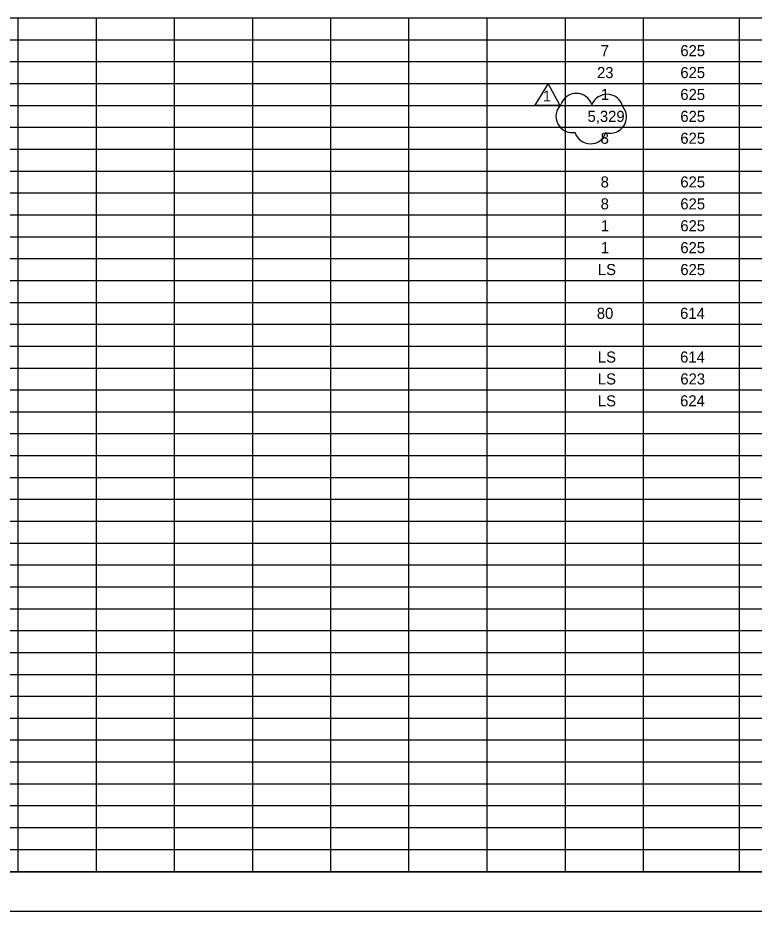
# Model space of a CAD drawing. Extents: x 0 to 34, y 0 to 22.
# Drawn here: x 7.49 to 16.91, y 0 to 11.42 of the extents above; entities that cross this region are included whole.
import ezdxf

# ---------------------------------------------------------------- set-up
doc = ezdxf.new("R2010")
doc.units = 0
for name, color, linetype in [('Default', 7, 'Continuous'), ('SH_Border', 7, 'Continuous'), ('SH_Cut_Line', 7, 'Continuous'), ('SH_Text', 7, 'Continuous')]:
    doc.layers.add(name, color=color, linetype=linetype)

msp = doc.modelspace()

# ---------------------------------------------------------------- linework, layer by layer
at = {"layer": 'Default'}
msp.add_lwpolyline([(14.273, 10.587), (14.102, 10.308), (14.422, 10.307)], close=True, dxfattribs=at)
for centre, start, end in [((14.633, 10.251), 17.5, 162.5), ((15.026, 10.239), 14.1039, 159.1039), ((14.581, 10.165), 134.5743, 279.5743), ((15.067, 10.158), 254.4905, 39.4905), ((14.814, 10.022), 197.0681, 342.0681)]:
    msp.add_arc(centre, 0.208, start, end, dxfattribs=at)
at = {"layer": 'SH_Border'}
msp.add_lwpolyline([(1.5, 21.5), (33.5, 21.5), (33.5, 0.5), (1.5, 0.5)], close=True, dxfattribs=at)
at = {"layer": 'SH_Cut_Line'}
msp.add_lwpolyline([(0, 0), (34, 0), (34, 22), (0, 22)], close=True, dxfattribs=at)
at = {"layer": 'SH_Text'}
for p, q in [((6.496, 11.424), (7.495, 11.424)), ((7.495, 11.424), (8.494, 11.424)), ((7.495, 11.424), (7.495, 10.305)), ((8.494, 11.424), (13.49, 11.424)), ((8.494, 11.424), (8.494, 10.305)), ((9.493, 11.424), (9.493, 10.305)), ((10.492, 11.424), (10.492, 10.305)), ((11.491, 11.424), (11.491, 10.305)), ((12.49, 11.424), (12.49, 10.305)), ((13.49, 11.424), (31.057, 11.424)), ((13.49, 11.424), (13.49, 10.305)), ((14.489, 11.424), (14.489, 10.305)), ((15.488, 11.424), (15.488, 10.305)), ((16.715, 11.424), (16.715, 10.305)), ((6.496, 11.145), (7.495, 11.145)), ((7.495, 11.145), (8.494, 11.145)), ((8.494, 11.145), (13.49, 11.145)), ((13.49, 11.145), (31.057, 11.145)), ((6.496, 10.865), (7.495, 10.865)), ((7.495, 10.865), (8.494, 10.865)), ((8.494, 10.865), (13.49, 10.865)), ((13.49, 10.865), (31.057, 10.865)), ((6.496, 10.585), (7.495, 10.585)), ((7.495, 10.585), (8.494, 10.585)), ((8.494, 10.585), (13.49, 10.585)), ((13.49, 10.585), (31.057, 10.585)), ((6.496, 10.305), (7.495, 10.305)), ((7.495, 10.305), (8.494, 10.305)), ((7.495, 10.305), (7.495, 10.025)), ((8.494, 10.305), (13.49, 10.305)), ((8.494, 10.305), (8.494, 10.025)), ((9.493, 10.305), (9.493, 10.025)), ((10.492, 10.305), (10.492, 10.025)), ((11.491, 10.305), (11.491, 10.025)), ((12.49, 10.305), (12.49, 10.025)), ((13.49, 10.305), (31.057, 10.305)), ((13.49, 10.305), (13.49, 10.025)), ((14.489, 10.305), (14.489, 10.025)), ((15.488, 10.305), (15.488, 10.025)), ((16.715, 10.305), (16.715, 10.025)), ((6.496, 10.025), (7.495, 10.025)), ((7.495, 10.025), (8.494, 10.025)), ((7.495, 10.025), (7.495, 9.745)), ((8.494, 10.025), (13.49, 10.025)), ((8.494, 10.025), (8.494, 9.745)), ((9.493, 10.025), (9.493, 9.745)), ((10.492, 10.025), (10.492, 9.745)), ((11.491, 10.025), (11.491, 9.745)), ((12.49, 10.025), (12.49, 9.745)), ((13.49, 10.025), (31.057, 10.025)), ((13.49, 10.025), (13.49, 9.745)), ((14.489, 10.025), (14.489, 9.745)), ((15.488, 10.025), (15.488, 9.745)), ((16.715, 10.025), (16.715, 9.745)), ((6.496, 9.745), (7.495, 9.745)), ((7.495, 9.745), (8.494, 9.745)), ((7.495, 9.745), (7.495, 8.906)), ((8.494, 9.745), (13.49, 9.745)), ((8.494, 9.745), (8.494, 8.906)), ((9.493, 9.745), (9.493, 8.906)), ((10.492, 9.745), (10.492, 8.906)), ((11.491, 9.745), (11.491, 8.906)), ((12.49, 9.745), (12.49, 8.906)), ((13.49, 9.745), (31.057, 9.745)), ((13.49, 9.745), (13.49, 8.906)), ((14.489, 9.745), (14.489, 8.906)), ((15.488, 9.745), (15.488, 8.906)), ((16.715, 9.745), (16.715, 8.906)), ((6.496, 9.465), (7.495, 9.465)), ((7.495, 9.465), (8.494, 9.465)), ((8.494, 9.465), (13.49, 9.465)), ((13.49, 9.465), (31.057, 9.465)), ((6.496, 9.185), (7.495, 9.185)), ((7.495, 9.185), (8.494, 9.185)), ((8.494, 9.185), (13.49, 9.185)), ((13.49, 9.185), (31.057, 9.185)), ((6.496, 8.906), (7.495, 8.906)), ((7.495, 8.906), (8.494, 8.906)), ((7.495, 8.906), (7.495, 8.346)), ((8.494, 8.906), (13.49, 8.906)), ((8.494, 8.906), (8.494, 8.346)), ((9.493, 8.906), (9.493, 8.346)), ((10.492, 8.906), (10.492, 8.346)), ((11.491, 8.906), (11.491, 8.346)), ((12.49, 8.906), (12.49, 8.346)), ((13.49, 8.906), (31.057, 8.906)), ((13.49, 8.906), (13.49, 8.346)), ((14.489, 8.906), (14.489, 8.346)), ((15.488, 8.906), (15.488, 8.346)), ((16.715, 8.906), (16.715, 8.346)), ((6.496, 8.626), (7.495, 8.626)), ((7.495, 8.626), (8.494, 8.626)), ((8.494, 8.626), (13.49, 8.626)), ((13.49, 8.626), (31.057, 8.626)), ((6.496, 8.346), (7.495, 8.346)), ((7.495, 8.346), (8.494, 8.346)), ((7.495, 8.346), (7.495, 7.506)), ((8.494, 8.346), (13.49, 8.346)), ((8.494, 8.346), (8.494, 7.506)), ((9.493, 8.346), (9.493, 7.506)), ((10.492, 8.346), (10.492, 7.506)), ((11.491, 8.346), (11.491, 7.506)), ((12.49, 8.346), (12.49, 7.506)), ((13.49, 8.346), (31.057, 8.346)), ((13.49, 8.346), (13.49, 7.506)), ((14.489, 8.346), (14.489, 7.506)), ((15.488, 8.346), (15.488, 7.506)), ((16.715, 8.346), (16.715, 7.506)), ((6.496, 8.066), (7.495, 8.066)), ((7.495, 8.066), (8.494, 8.066)), ((8.494, 8.066), (13.49, 8.066)), ((13.49, 8.066), (31.057, 8.066)), ((6.496, 7.786), (7.495, 7.786)), ((7.495, 7.786), (8.494, 7.786)), ((8.494, 7.786), (13.49, 7.786)), ((13.49, 7.786), (31.057, 7.786)), ((6.496, 7.506), (7.495, 7.506)), ((7.495, 7.506), (8.494, 7.506)), ((7.495, 7.506), (7.495, 6.946)), ((8.494, 7.506), (13.49, 7.506)), ((8.494, 7.506), (8.494, 6.946)), ((9.493, 7.506), (9.493, 6.946)), ((10.492, 7.506), (10.492, 6.946)), ((11.491, 7.506), (11.491, 6.946)), ((12.49, 7.506), (12.49, 6.946)), ((13.49, 7.506), (31.057, 7.506)), ((13.49, 7.506), (13.49, 6.946)), ((14.489, 7.506), (14.489, 6.946)), ((15.488, 7.506), (15.488, 6.946)), ((16.715, 7.506), (16.715, 6.946)), ((6.496, 7.226), (7.495, 7.226)), ((7.495, 7.226), (8.494, 7.226)), ((8.494, 7.226), (13.49, 7.226)), ((13.49, 7.226), (31.057, 7.226)), ((6.496, 6.946), (7.495, 6.946)), ((7.495, 6.946), (8.494, 6.946)), ((7.495, 6.946), (7.495, 6.107)), ((8.494, 6.946), (13.49, 6.946)), ((8.494, 6.946), (8.494, 6.107)), ((9.493, 6.946), (9.493, 6.107)), ((10.492, 6.946), (10.492, 6.107)), ((11.491, 6.946), (11.491, 6.107)), ((12.49, 6.946), (12.49, 6.107)), ((13.49, 6.946), (31.057, 6.946)), ((13.49, 6.946), (13.49, 6.107)), ((14.489, 6.946), (14.489, 6.107)), ((15.488, 6.946), (15.488, 6.107)), ((16.715, 6.946), (16.715, 6.107)), ((6.496, 6.667), (7.495, 6.667)), ((7.495, 6.667), (8.494, 6.667)), ((8.494, 6.667), (13.49, 6.667)), ((13.49, 6.667), (31.057, 6.667)), ((6.496, 6.387), (7.495, 6.387)), ((7.495, 6.387), (8.494, 6.387)), ((8.494, 6.387), (13.49, 6.387)), ((13.49, 6.387), (31.057, 6.387)), ((6.496, 6.107), (7.495, 6.107)), ((7.495, 6.107), (8.494, 6.107)), ((7.495, 6.107), (7.495, 4.987)), ((8.494, 6.107), (13.49, 6.107)), ((8.494, 6.107), (8.494, 4.987)), ((9.493, 6.107), (9.493, 4.987)), ((10.492, 6.107), (10.492, 4.987)), ((11.491, 6.107), (11.491, 4.987)), ((12.49, 6.107), (12.49, 4.987)), ((13.49, 6.107), (31.057, 6.107)), ((13.49, 6.107), (13.49, 4.987)), ((14.489, 6.107), (14.489, 4.987)), ((15.488, 6.107), (15.488, 4.987)), ((16.715, 6.107), (16.715, 4.987)), ((6.496, 5.827), (7.495, 5.827)), ((7.495, 5.827), (8.494, 5.827)), ((8.494, 5.827), (13.49, 5.827)), ((13.49, 5.827), (31.057, 5.827)), ((6.496, 5.547), (7.495, 5.547)), ((7.495, 5.547), (8.494, 5.547)), ((8.494, 5.547), (13.49, 5.547)), ((13.49, 5.547), (31.057, 5.547)), ((6.496, 5.267), (7.495, 5.267)), ((7.495, 5.267), (8.494, 5.267)), ((8.494, 5.267), (13.49, 5.267)), ((13.49, 5.267), (31.057, 5.267)), ((6.496, 4.987), (7.495, 4.987)), ((7.495, 4.987), (8.494, 4.987)), ((7.495, 4.987), (7.495, 4.707)), ((8.494, 4.987), (13.49, 4.987)), ((8.494, 4.987), (8.494, 4.707)), ((9.493, 4.987), (9.493, 4.707)), ((10.492, 4.987), (10.492, 4.707)), ((11.491, 4.987), (11.491, 4.707)), ((12.49, 4.987), (12.49, 4.707)), ((13.49, 4.987), (31.057, 4.987)), ((13.49, 4.987), (13.49, 4.707)), ((14.489, 4.987), (14.489, 4.707)), ((15.488, 4.987), (15.488, 4.707)), ((16.715, 4.987), (16.715, 4.707)), ((6.496, 4.707), (7.495, 4.707)), ((7.495, 4.707), (8.494, 4.707)), ((7.495, 4.707), (7.495, 3.588)), ((8.494, 4.707), (13.49, 4.707)), ((8.494, 4.707), (8.494, 3.588)), ((9.493, 4.707), (9.493, 3.588)), ((10.492, 4.707), (10.492, 3.588)), ((11.491, 4.707), (11.491, 3.588)), ((12.49, 4.707), (12.49, 3.588)), ((13.49, 4.707), (31.057, 4.707)), ((13.49, 4.707), (13.49, 3.588)), ((14.489, 4.707), (14.489, 3.588)), ((15.488, 4.707), (15.488, 3.588)), ((16.715, 4.707), (16.715, 3.588)), ((6.496, 4.428), (7.495, 4.428)), ((7.495, 4.428), (8.494, 4.428)), ((8.494, 4.428), (13.49, 4.428)), ((13.49, 4.428), (31.057, 4.428)), ((6.496, 4.148), (7.495, 4.148)), ((7.495, 4.148), (8.494, 4.148)), ((8.494, 4.148), (13.49, 4.148)), ((13.49, 4.148), (31.057, 4.148)), ((6.496, 3.868), (7.495, 3.868)), ((7.495, 3.868), (8.494, 3.868)), ((8.494, 3.868), (13.49, 3.868)), ((13.49, 3.868), (31.057, 3.868)), ((6.496, 3.588), (7.495, 3.588)), ((7.495, 3.588), (8.494, 3.588)), ((7.495, 3.588), (7.495, 3.308)), ((8.494, 3.588), (13.49, 3.588)), ((8.494, 3.588), (8.494, 3.308)), ((9.493, 3.588), (9.493, 3.308)), ((10.492, 3.588), (10.492, 3.308)), ((11.491, 3.588), (11.491, 3.308)), ((12.49, 3.588), (12.49, 3.308)), ((13.49, 3.588), (31.057, 3.588)), ((13.49, 3.588), (13.49, 3.308)), ((14.489, 3.588), (14.489, 3.308)), ((15.488, 3.588), (15.488, 3.308)), ((16.715, 3.588), (16.715, 3.308)), ((6.496, 3.308), (7.495, 3.308)), ((7.495, 3.308), (8.494, 3.308)), ((7.495, 3.308), (7.495, 2.189)), ((8.494, 3.308), (13.49, 3.308)), ((8.494, 3.308), (8.494, 2.189)), ((9.493, 3.308), (9.493, 2.189)), ((10.492, 3.308), (10.492, 2.189)), ((11.491, 3.308), (11.491, 2.189)), ((12.49, 3.308), (12.49, 2.189)), ((13.49, 3.308), (31.057, 3.308)), ((13.49, 3.308), (13.49, 2.189)), ((14.489, 3.308), (14.489, 2.189)), ((15.488, 3.308), (15.488, 2.189)), ((16.715, 3.308), (16.715, 2.189)), ((6.496, 3.028), (7.495, 3.028)), ((7.495, 3.028), (8.494, 3.028)), ((8.494, 3.028), (13.49, 3.028)), ((13.49, 3.028), (31.057, 3.028)), ((6.496, 2.748), (7.495, 2.748)), ((7.495, 2.748), (8.494, 2.748)), ((8.494, 2.748), (13.49, 2.748)), ((13.49, 2.748), (31.057, 2.748)), ((6.496, 2.468), (7.495, 2.468)), ((7.495, 2.468), (8.494, 2.468)), ((8.494, 2.468), (13.49, 2.468)), ((13.49, 2.468), (31.057, 2.468)), ((6.496, 2.189), (7.495, 2.189)), ((7.495, 2.189), (8.494, 2.189)), ((7.495, 2.189), (7.495, 1.909)), ((8.494, 2.189), (13.49, 2.189)), ((8.494, 2.189), (8.494, 1.909)), ((9.493, 2.189), (9.493, 1.909)), ((10.492, 2.189), (10.492, 1.909)), ((11.491, 2.189), (11.491, 1.909)), ((12.49, 2.189), (12.49, 1.909)), ((13.49, 2.189), (31.057, 2.189)), ((13.49, 2.189), (13.49, 1.909)), ((14.489, 2.189), (14.489, 1.909)), ((15.488, 2.189), (15.488, 1.909)), ((16.715, 2.189), (16.715, 1.909)), ((6.496, 1.909), (7.495, 1.909)), ((7.495, 1.909), (8.494, 1.909)), ((7.495, 1.909), (7.495, 0.789)), ((8.494, 1.909), (13.49, 1.909)), ((8.494, 1.909), (8.494, 0.789)), ((9.493, 1.909), (9.493, 0.789)), ((10.492, 1.909), (10.492, 0.789)), ((11.491, 1.909), (11.491, 0.789)), ((12.49, 1.909), (12.49, 0.789)), ((13.49, 1.909), (31.057, 1.909)), ((13.49, 1.909), (13.49, 0.789)), ((14.489, 1.909), (14.489, 0.789)), ((15.488, 1.909), (15.488, 0.789)), ((16.715, 1.909), (16.715, 0.789)), ((6.496, 1.629), (7.495, 1.629)), ((7.495, 1.629), (8.494, 1.629)), ((8.494, 1.629), (13.49, 1.629)), ((13.49, 1.629), (31.057, 1.629)), ((6.496, 1.349), (7.495, 1.349)), ((7.495, 1.349), (8.494, 1.349)), ((8.494, 1.349), (13.49, 1.349)), ((13.49, 1.349), (31.057, 1.349)), ((6.496, 1.069), (7.495, 1.069)), ((7.495, 1.069), (8.494, 1.069)), ((8.494, 1.069), (13.49, 1.069)), ((13.49, 1.069), (31.057, 1.069)), ((6.496, 0.789), (7.495, 0.789)), ((7.495, 0.789), (8.494, 0.789)), ((7.495, 0.789), (7.495, 0.509)), ((8.494, 0.789), (13.49, 0.789)), ((8.494, 0.789), (8.494, 0.509)), ((9.493, 0.789), (9.493, 0.509)), ((10.492, 0.789), (10.492, 0.509)), ((11.491, 0.789), (11.491, 0.509)), ((12.49, 0.789), (12.49, 0.509)), ((13.49, 0.789), (31.057, 0.789)), ((13.49, 0.789), (13.49, 0.509)), ((14.489, 0.789), (14.489, 0.509)), ((15.488, 0.789), (15.488, 0.509)), ((16.715, 0.789), (16.715, 0.509)), ((6.496, 0.509), (7.495, 0.509)), ((7.495, 0.509), (8.494, 0.509)), ((8.494, 0.509), (13.49, 0.509)), ((13.49, 0.509), (31.057, 0.509))]:
    msp.add_line(p, q, dxfattribs=at)

# ---------------------------------------------------------------- texts
at = {"layer": 'Default'}
msp.add_text('1', height=0.14, dxfattribs=at).set_placement((14.205, 10.355))
at = {"layer": 'SH_Text'}
for s, height, p in [('7', 0.142, (14.945, 10.934)), ('625', 0.1416, (15.963, 10.934)), ('23', 0.1416, (14.898, 10.654)), ('625', 0.1416, (15.963, 10.654)), ('1', 0.142, (14.946, 10.374)), ('625', 0.1416, (15.963, 10.374)), ('5,329', 0.1416, (14.777, 10.094)), ('625', 0.1416, (15.963, 10.094)), ('8', 0.142, (14.944, 9.814)), ('625', 0.1416, (15.963, 9.814)), ('8', 0.142, (14.944, 9.255)), ('625', 0.1416, (15.963, 9.255)), ('8', 0.142, (14.944, 8.975)), ('625', 0.1416, (15.963, 8.975)), ('1', 0.142, (14.946, 8.695)), ('625', 0.1416, (15.963, 8.695)), ('1', 0.142, (14.946, 8.415)), ('625', 0.1416, (15.963, 8.415)), ('LS', 0.1416, (14.909, 8.135)), ('625', 0.1416, (15.963, 8.135)), ('80', 0.1416, (14.895, 7.575)), ('614', 0.1416, (15.96, 7.575)), ('LS', 0.1416, (14.909, 7.016)), ('614', 0.1416, (15.96, 7.016)), ('LS', 0.1416, (14.909, 6.736)), ('623', 0.1416, (15.963, 6.736)), ('LS', 0.1416, (14.909, 6.456)), ('624', 0.1416, (15.96, 6.456))]:
    msp.add_text(s, height=height, dxfattribs=at).set_placement(p)

doc.saveas('drawing.dxf')
